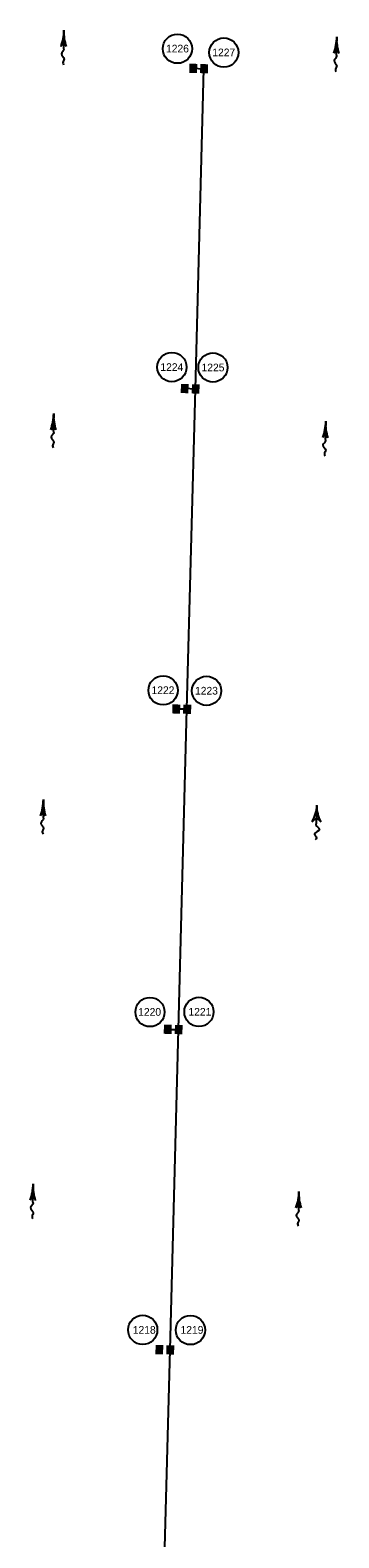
# Model space of a CAD drawing. Extents: x 594534 to 598564, y 225861 to 236229.
# Drawn here: x 598323 to 598564, y 235052 to 236229 of the extents above; entities that cross this region are included whole.
import ezdxf

# ---------------------------------------------------------------- set-up
doc = ezdxf.new("R2010")
doc.units = 0
for name, color, linetype in [('P_DRN_Flow', 7, 'Continuous'), ('P_DRN_Inlet', 7, 'Continuous'), ('P_DRN_SS_UG', 7, 'Continuous'), ('P_DRN_Text', 7, 'Continuous')]:
    doc.layers.add(name, color=color, linetype=linetype)

msp = doc.modelspace()

# ---------------------------------------------------------------- linework, layer by layer
at = {"layer": 'P_DRN_Flow'}
for p, q in [((598349.5, 236228.8), (598349.2, 236214.7)), ((598562.3, 236223.5), (598561.9, 236209.4)), ((598341.6, 235929.8), (598341.3, 235915.7)), ((598553.7, 235923.6), (598553.3, 235909.5)), ((598333.6, 235628.6), (598333.3, 235614.5)), ((598546.8, 235623.9), (598546.4, 235609.8)), ((598325.5, 235328.6), (598325.2, 235314.5)), ((598532.8, 235322.8), (598532.4, 235308.7))]:
    msp.add_line(p, q, dxfattribs=at)
for points in [[(598351.3, 236215.9), (598349.3, 236219.2), (598347.3, 236216)], [(598564, 236210.7), (598562, 236213.9), (598560, 236210.8)], [(598343.3, 235917), (598341.4, 235920.2), (598339.3, 235917)], [(598555.3, 235910.8), (598553.4, 235914.1), (598551.3, 235910.9)], [(598335.3, 235615.8), (598333.4, 235619), (598331.3, 235615.8)], [(598543.1, 235611.2), (598546.6, 235614.3), (598549.8, 235611.1)], [(598327.3, 235315.8), (598325.3, 235319), (598323.3, 235315.8)], [(598534.5, 235309.9), (598532.6, 235313.2), (598530.5, 235310)]]:
    msp.add_lwpolyline(points, dxfattribs=at)
for centre, start, end in [((598307.6, 236229.6), 341.068, 358.8303), ((598391.5, 236227.9), 178.8303, 196.5926), ((598520.4, 236224.7), 340.6574, 358.4197), ((598604.2, 236222.4), 178.4197, 196.182), ((598299.6, 235930.6), 341.068, 358.8303), ((598383.5, 235928.9), 178.8303, 196.5926), ((598511.8, 235924.8), 340.6574, 358.4197), ((598595.6, 235922.5), 178.4197, 196.182), ((598291.6, 235629.4), 341.068, 358.8303), ((598375.5, 235627.7), 178.8303, 196.5926), ((598283.6, 235329.5), 341.068, 358.8303), ((598367.5, 235327.7), 178.8303, 196.5926), ((598490.9, 235323.9), 340.6574, 358.4197), ((598574.8, 235321.6), 178.4197, 196.182)]:
    msp.add_arc(centre, 42, start, end, dxfattribs=at)
for centre, major_axis, start_param, end_param in [((598476.4, 235625.9), (70.4, -1.9), 5.973174, 6.283185), ((598617.2, 235622), (-70.4, 1.9), 0, 0.310011)]:
    msp.add_ellipse(centre, major_axis=major_axis, ratio=0.595988, start_param=start_param, end_param=end_param, dxfattribs=at)
for points in [[(598349.2, 236214.7), (598349.5, 236213.9), (598347.6, 236210.3), (598349.7, 236206.3), (598348.7, 236203.5), (598349.3, 236201.8)], [(598561.9, 236209.4), (598562.2, 236208.6), (598560.2, 236205), (598562.3, 236201.1), (598561.3, 236198.3), (598561.9, 236196.5)], [(598341.3, 235915.7), (598341.6, 235914.9), (598339.6, 235911.3), (598341.7, 235907.3), (598340.7, 235904.5), (598341.3, 235902.8)], [(598553.3, 235909.5), (598553.6, 235908.7), (598551.6, 235905.2), (598553.7, 235901.2), (598552.7, 235898.4), (598553.3, 235896.6)], [(598333.3, 235614.5), (598333.6, 235613.7), (598331.6, 235610.1), (598333.7, 235606.1), (598332.7, 235603.3), (598333.3, 235601.6)], [(598546.4, 235609.8), (598545.9, 235609), (598548.9, 235605.4), (598545.1, 235601.5), (598546.6, 235598.7), (598545.5, 235597)], [(598325.2, 235314.5), (598325.5, 235313.7), (598323.6, 235310.1), (598325.7, 235306.1), (598324.7, 235303.3), (598325.3, 235301.6)], [(598532.4, 235308.7), (598532.7, 235307.9), (598530.8, 235304.3), (598532.8, 235300.3), (598531.8, 235297.5), (598532.4, 235295.8)]]:
    msp.add_spline(points, degree=3, dxfattribs=at)
at = {"layer": 'P_DRN_Inlet'}
for p, q in [((598448.1, 236202.4), (598447.9, 236195.6)), ((598449, 236202.4), (598448.8, 236195.6)), ((598449.9, 236202.4), (598449.7, 236195.5)), ((598450.8, 236202.4), (598450.6, 236195.5)), ((598451.7, 236202.4), (598451.5, 236195.5)), ((598452.6, 236202.3), (598452.4, 236195.5)), ((598456.6, 236202.2), (598456.4, 236195.4)), ((598457.5, 236202.2), (598457.3, 236195.3)), ((598458.4, 236202.2), (598458.2, 236195.3)), ((598459.3, 236202.2), (598459.1, 236195.3)), ((598460.2, 236202.1), (598460, 236195.3)), ((598461.1, 236202.1), (598460.9, 236195.2)), ((598441.5, 235952.6), (598441.3, 235945.7)), ((598442.4, 235952.6), (598442.2, 235945.7)), ((598443.3, 235952.6), (598443.1, 235945.7)), ((598444.2, 235952.5), (598444, 235945.7)), ((598445.1, 235952.5), (598444.9, 235945.6)), ((598446, 235952.5), (598445.8, 235945.6)), ((598450, 235952.3), (598449.8, 235945.5)), ((598450.9, 235952.3), (598450.7, 235945.4)), ((598451.8, 235952.3), (598451.6, 235945.4)), ((598452.7, 235952.2), (598452.5, 235945.4)), ((598453.6, 235952.2), (598453.4, 235945.3)), ((598454.5, 235952.2), (598454.3, 235945.3)), ((598434.9, 235702.6), (598434.7, 235695.8)), ((598435.8, 235702.6), (598435.6, 235695.7)), ((598436.7, 235702.6), (598436.5, 235695.7)), ((598437.6, 235702.6), (598437.4, 235695.7)), ((598438.5, 235702.5), (598438.3, 235695.7)), ((598439.4, 235702.5), (598439.2, 235695.6)), ((598443.4, 235702.4), (598443.2, 235695.5)), ((598444.3, 235702.4), (598444.1, 235695.5)), ((598445.2, 235702.4), (598445, 235695.5)), ((598446.1, 235702.3), (598445.9, 235695.5)), ((598447, 235702.3), (598446.8, 235695.4)), ((598447.9, 235702.3), (598447.7, 235695.4)), ((598428.3, 235452.7), (598428.1, 235445.9)), ((598429.2, 235452.7), (598429, 235445.8)), ((598430.1, 235452.7), (598429.9, 235445.8)), ((598431, 235452.6), (598430.8, 235445.8)), ((598431.9, 235452.6), (598431.7, 235445.7)), ((598432.8, 235452.6), (598432.6, 235445.7)), ((598436.8, 235452.5), (598436.6, 235445.6)), ((598437.7, 235452.5), (598437.5, 235445.6)), ((598438.6, 235452.4), (598438.4, 235445.6)), ((598439.5, 235452.4), (598439.3, 235445.6)), ((598440.4, 235452.4), (598440.2, 235445.5)), ((598441.3, 235452.4), (598441.1, 235445.5)), ((598421.7, 235202.8), (598421.5, 235195.9)), ((598422.6, 235202.8), (598422.4, 235195.9)), ((598423.5, 235202.8), (598423.3, 235195.9)), ((598424.4, 235202.7), (598424.2, 235195.9)), ((598425.3, 235202.7), (598425.1, 235195.8)), ((598426.2, 235202.7), (598426, 235195.8)), ((598430.2, 235202.6), (598430, 235195.7)), ((598431.1, 235202.6), (598430.9, 235195.7)), ((598432, 235202.5), (598431.8, 235195.7)), ((598432.9, 235202.5), (598432.7, 235195.6)), ((598433.8, 235202.5), (598433.6, 235195.6)), ((598434.7, 235202.5), (598434.5, 235195.6))]:
    msp.add_line(p, q, dxfattribs=at)
for points in [[(598449.3, 236200), (598449.2, 236198), (598451.2, 236197.9), (598451.3, 236199.9)], [(598457.8, 236199.8), (598457.7, 236197.8), (598459.7, 236197.7), (598459.8, 236199.7)], [(598442.7, 235950.1), (598442.6, 235948.1), (598444.6, 235948.1), (598444.7, 235950.1)], [(598451.2, 235949.9), (598451.1, 235947.9), (598453.1, 235947.8), (598453.2, 235949.8)], [(598436.1, 235700.2), (598436, 235698.2), (598438, 235698.1), (598438.1, 235700.1)], [(598444.6, 235699.9), (598444.5, 235697.9), (598446.5, 235697.9), (598446.6, 235699.9)], [(598429.5, 235450.3), (598429.4, 235448.3), (598431.4, 235448.2), (598431.5, 235450.2)], [(598438, 235450), (598437.9, 235448), (598439.9, 235448), (598440, 235450)], [(598422.9, 235200.3), (598422.8, 235198.3), (598424.8, 235198.3), (598424.9, 235200.3)], [(598431.4, 235200.1), (598431.3, 235198.1), (598433.3, 235198.1), (598433.4, 235200.1)]]:
    msp.add_lwpolyline(points, close=True, dxfattribs=at)
at = {"layer": 'P_DRN_SS_UG'}
for p, q in [((598450.2, 236199), (598458.7, 236198.7)), ((598452.1, 235948.8), (598458.7, 236198.7)), ((598452.1, 235948.8), (598443.6, 235949.1)), ((598445.5, 235698.9), (598452.1, 235948.8)), ((598445.5, 235698.9), (598437.1, 235699.1)), ((598439, 235449), (598445.5, 235698.9)), ((598432.4, 235199.1), (598439, 235449)), ((598425.9, 234954.2), (598432.4, 235199.1))]:
    msp.add_line(p, q, dxfattribs=at)
msp.add_lwpolyline([(598430.5, 235449.2), (598439, 235449)], dxfattribs=at)
at = {"layer": 'P_DRN_Text'}
for centre in [(598438.1, 236214.3), (598474.3, 236211.3), (598433.8, 235965.9), (598465.8, 235965.6), (598426.9, 235713.7), (598460.8, 235713.3), (598416.7, 235462.7), (598454.9, 235462.8), (598411, 235214.7), (598448.2, 235214.6)]:
    msp.add_circle(centre, 11.4, dxfattribs=at)

# ---------------------------------------------------------------- texts
for s, p in [('1226', (598429.2, 236211.4)), ('1227', (598465.3, 236208.4)), ('1224', (598424.8, 235962.9)), ('1225', (598456.9, 235962.6)), ('1222', (598417.9, 235710.8)), ('1223', (598451.8, 235710.4)), ('1220', (598407.5, 235459.8)), ('1221', (598446.7, 235459.9)), ('1218', (598403.3, 235211.7)), ('1219', (598440.5, 235211.7))]:
    msp.add_text(s, height=6, dxfattribs=at).set_placement(p)

doc.saveas('drawing.dxf')
